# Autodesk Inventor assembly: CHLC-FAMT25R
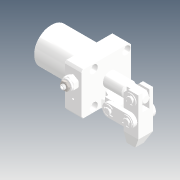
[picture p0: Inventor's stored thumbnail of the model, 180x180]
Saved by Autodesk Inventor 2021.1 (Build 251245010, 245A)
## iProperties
Created: 2019-04
Part Number: CHLC-FAMT25R
Description: STEP AP214
Document SubType Name: Assembly
Designer: user
Title: CHLC-FAMT25R.STEP
Revision Number: ÈÎºÎ
Sending System: SolidWorks 2016
Preprocessor: SwSTEP 2.0
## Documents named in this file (11)
- D:\Vault_2016\Projekty\Clamptek\Hydraulic\CHLC\CHLC-25\Inventor\CHLC-FAMT25R\CHLC-FAMT25R.iam
- D:\Vault_2016\Projekty\Clamptek\Hydraulic\CHLC\CHLC-25\Inventor\CHLC-FAMT25R\CHLC-FAMT25BT.ipt
- D:\Vault_2016\Projekty\Clamptek\Hydraulic\CHLC\CHLC-25\Inventor\CHLC-FAMT25R\CHLC-25CX.ipt
- D:\Vault_2016\Projekty\Clamptek\Hydraulic\CHLC\CHLC-25\Inventor\CHLC-FAMT25R\CHLC-25DX.ipt
- D:\Vault_2016\Projekty\Clamptek\Hydraulic\CHLC\CHLC-25\Inventor\CHLC-FAMT25R\CHLC-25HSG.ipt
- D:\Vault_2016\Projekty\Clamptek\Hydraulic\CHLC\CHLC-25\Inventor\CHLC-FAMT25R\CHLC-25KKDC.ipt
- D:\Vault_2016\Projekty\Clamptek\Hydraulic\CHLC\CHLC-25\Inventor\CHLC-FAMT25R\CHLC-25LG.ipt
- D:\Vault_2016\Projekty\Clamptek\Hydraulic\CHLC\CHLC-25\Inventor\CHLC-FAMT25R\CHLC-25ZC.ipt
- D:\Vault_2016\Projekty\Clamptek\Hydraulic\CHLC\CHLC-25\Inventor\CHLC-FAMT25R\CHLC-25ZC-HAN.ipt
- D:\Vault_2016\Projekty\Clamptek\Hydraulic\CHLC\CHLC-25\Inventor\CHLC-FAMT25R\CZL10µ÷ËÙ·§.ipt
- D:\Vault_2016\Projekty\Clamptek\Hydraulic\CHLC\CHLC-25\Inventor\CHLC-FAMT25R\Ñ¹±Û.ipt
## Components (17 placed, 17 different names)
1. CHLC-FAMT25BT_1
2. CHLC-25CX_2
3. CHLC-25DX_3
4. CHLC-25HSG_4
5. CHLC-25KKDC_5
6. CHLC-25LG_6
7. CHLC-25ZC_7
8. CHLC-25ZC-HAN_8
9. CZL10µ÷ËÙ·§_9
10. CHLC-25LG_10
11. CHLC-25KKDC_11
12. CHLC-25KKDC_12
13. CHLC-25KKDC_13
14. CHLC-25KKDC_14
15. CHLC-25KKDC_15
16. CHLC-25CX_16
17. Ñ¹±Û_17
